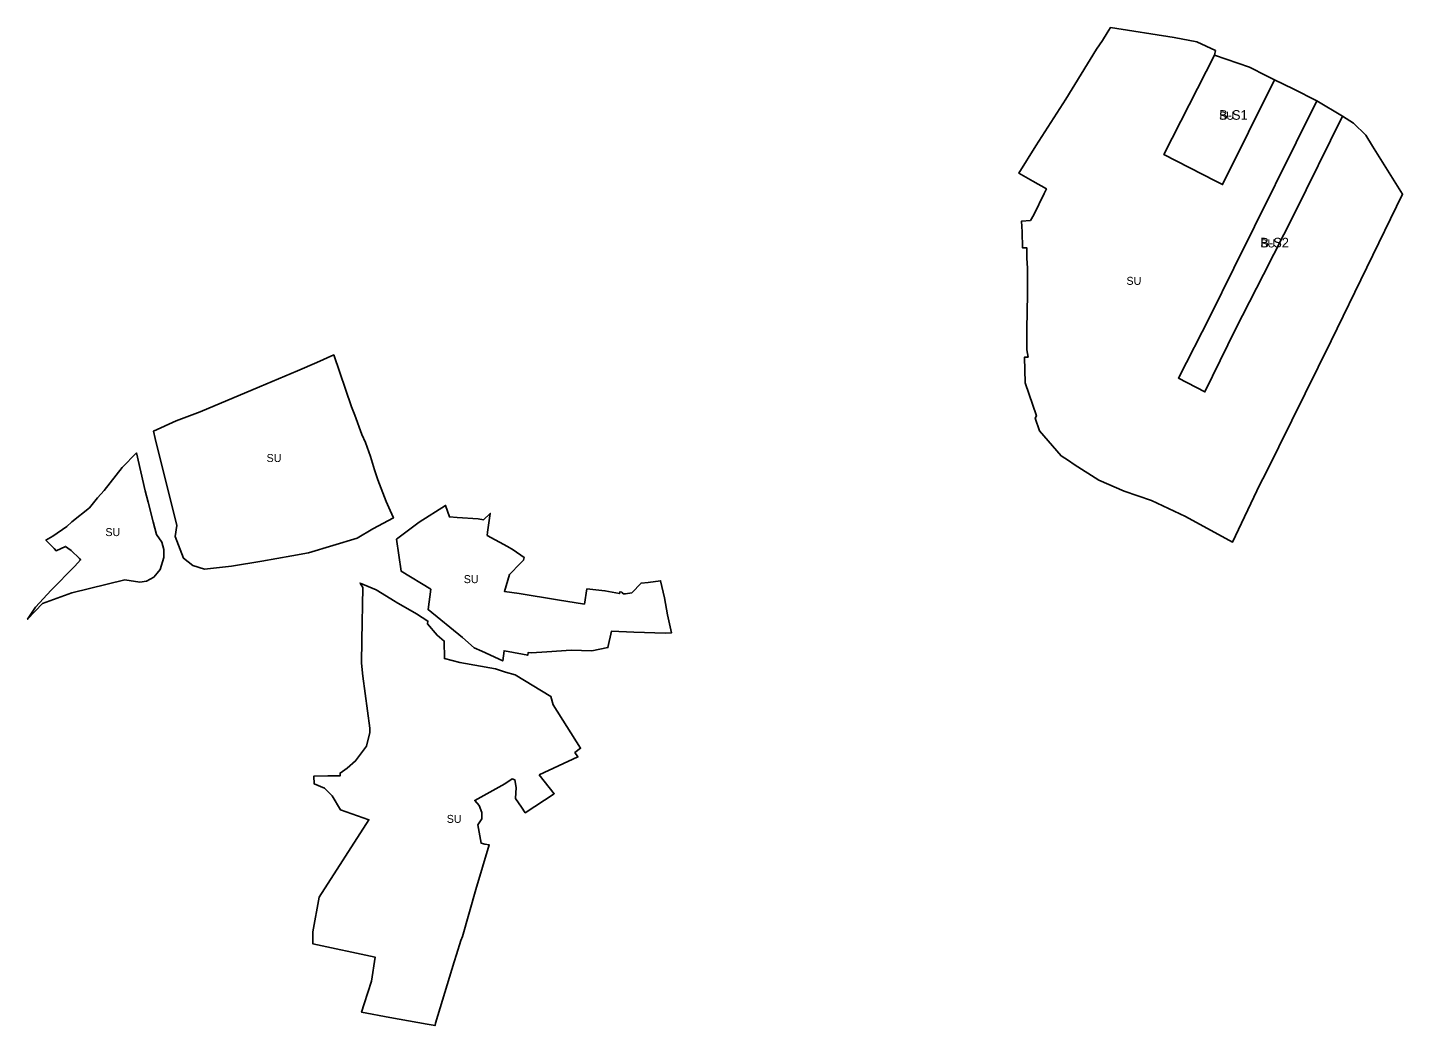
# Model space of a CAD drawing. Extents: x -532031 to -530019, y -1180236 to -1177276.
# Drawn here: x -531101 to -530242, y -1178607 to -1177983 of the extents above; entities that cross this region are included whole.
import ezdxf

# ---------------------------------------------------------------- set-up
doc = ezdxf.new("R2010")
doc.units = 0
for name, color, linetype in [('90480013', 7, 'Continuous'), ('90480023', 7, 'Continuous'), ('ID_navrh', 7, 'Continuous')]:
    doc.layers.add(name, color=color, linetype=linetype)

msp = doc.modelspace()

# ---------------------------------------------------------------- linework, layer by layer
at = {"layer": '90480013'}
for points in [[(-530359.2473, -1178079.28545), (-530354.5743, -1178081.67545), (-530322.1763, -1178016.13545), (-530310.4773, -1178021.80745), (-530295.6573, -1178029.24045), (-530347.5943, -1178133.89345), (-530362.2753, -1178163.84345), (-530382.1233, -1178202.62845), (-530365.5663, -1178211.24845), (-530346.3653, -1178172.03845), (-530328.9113, -1178137.78745), (-530309.7773, -1178100.23945), (-530279.6673, -1178038.82445), (-530272.6473, -1178043.32345), (-530265.0433, -1178050.75545), (-530260.7533, -1178057.60145), (-530242.0943, -1178087.56745), (-530286.6053, -1178179.34845), (-530327.4363, -1178262.14345), (-530331.3213, -1178269.18745), (-530348.3553, -1178305.24545), (-530377.6083, -1178289.27445), (-530398.9863, -1178279.22845), (-530415.9353, -1178273.23945), (-530431.9213, -1178266.47745), (-530447.2033, -1178256.72845), (-530450.7233, -1178254.20645), (-530455.4163, -1178251.34745), (-530468.9943, -1178235.54245), (-530471.6763, -1178227.80845), (-530470.8383, -1178226.29445), (-530477.8753, -1178205.60445), (-530478.2723, -1178189.46745), (-530476.0883, -1178189.46745), (-530476.9243, -1178184.96445), (-530476.7733, -1178171.79145), (-530476.5293, -1178150.45345), (-530476.3413, -1178134.01445), (-530476.7533, -1178127.57745), (-530476.9063, -1178121.16545), (-530479.5183, -1178121.22745), (-530479.7563, -1178111.25945), (-530480.2483, -1178104.64145), (-530474.6533, -1178104.17445), (-530472.5533, -1178100.49045), (-530465.9993, -1178087.34345), (-530464.6673, -1178084.36645), (-530473.1953, -1178079.44845), (-530481.9363, -1178074.52945), (-530471.2763, -1178057.42145), (-530452.4703, -1178028.18145), (-530433.2363, -1177996.96545), (-530429.6423, -1177991.66345), (-530426.6943, -1177986.79645), (-530424.5493, -1177983.47145), (-530384.7703, -1177989.73045), (-530370.5353, -1177992.46845), (-530359.0313, -1177997.94545), (-530359.6163, -1178000.68345), (-530391.1673, -1178062.95745)], [(-530973.8763, -1178320.29145), (-530990.7503, -1178322.07345), (-530998.0323, -1178319.75745), (-531003.8943, -1178315.30345), (-531009.0453, -1178301.76245), (-531007.9793, -1178294.81445), (-531021.4783, -1178240.47345), (-531022.7053, -1178235.84845), (-531008.4323, -1178229.27145), (-530993.3943, -1178223.78245), (-530956.3823, -1178208.15845), (-530932.6003, -1178198.07945), (-530920.5413, -1178192.87145), (-530909.9903, -1178188.16745), (-530898.8403, -1178220.60245), (-530896.8853, -1178225.83045), (-530892.3243, -1178237.81245), (-530890.1523, -1178242.82245), (-530887.1123, -1178251.75445), (-530884.5063, -1178260.03245), (-530882.4513, -1178266.30845), (-530877.2353, -1178279.79945), (-530874.7093, -1178285.46045), (-530872.6603, -1178290.05245), (-530885.4993, -1178296.92945), (-530895.3683, -1178302.65345), (-530925.7413, -1178311.91845), (-530936.1423, -1178313.72745), (-530955.0093, -1178317.00945)], [(-531017.3653, -1178305.16245), (-531016.2303, -1178309.71645), (-531016.2303, -1178314.72645), (-531018.5003, -1178322.24045), (-531020.4293, -1178324.63145), (-531022.3593, -1178327.02245), (-531026.8993, -1178329.52645), (-531031.2123, -1178330.20945), (-531040.5193, -1178328.84345), (-531073.6623, -1178336.81345), (-531092.0493, -1178343.64445), (-531101.3573, -1178353.43545), (-531096.2623, -1178345.92745), (-531086.5173, -1178335.30345), (-531071.8703, -1178320.14045), (-531068.1793, -1178316.33245), (-531068.9173, -1178315.48645), (-531074.0903, -1178310.50145), (-531076.1943, -1178309.03345), (-531077.5653, -1178307.86945), (-531083.4713, -1178310.61945), (-531084.7363, -1178309.13845), (-531087.1623, -1178306.70545), (-531089.8883, -1178303.97145), (-531085.4663, -1178301.51945), (-531076.8403, -1178295.37145), (-531073.6623, -1178292.41145), (-531062.7133, -1178283.82845), (-531057.6743, -1178277.56045), (-531053.4583, -1178272.96345), (-531042.1083, -1178258.48345), (-531033.2923, -1178249.40845), (-531027.7303, -1178273.15745), (-531026.0043, -1178280.13145), (-531022.8133, -1178292.41145), (-531020.7703, -1178300.38045)], [(-530819.7433, -1178290.70145), (-530816.3013, -1178291.26145), (-530812.1923, -1178287.22345), (-530813.9653, -1178298.97045), (-530814.1373, -1178301.03845), (-530801.3973, -1178308.03245), (-530797.8173, -1178309.99845), (-530791.0503, -1178314.80445), (-530791.4993, -1178316.55945), (-530793.1793, -1178318.44245), (-530800.2223, -1178325.50745), (-530803.3143, -1178336.01945), (-530794.0383, -1178337.39745), (-530770.1593, -1178341.36145), (-530753.3233, -1178343.94545), (-530751.7773, -1178334.46845), (-530740.5603, -1178335.55945), (-530731.3453, -1178337.35045), (-530731.0943, -1178336.21645), (-530729.9643, -1178336.46845), (-530729.0863, -1178337.47645), (-530727.5803, -1178337.47645), (-530723.6893, -1178336.84645), (-530717.8813, -1178330.82045), (-530713.4023, -1178330.41145), (-530705.7373, -1178329.31845), (-530703.2593, -1178340.00845), (-530701.4593, -1178350.73345), (-530698.9373, -1178361.95845), (-530702.6243, -1178362.20145), (-530722.4203, -1178361.45845), (-530736.4333, -1178360.93245), (-530738.6253, -1178371.09145), (-530748.6853, -1178373.06745), (-530761.5693, -1178372.72345), (-530776.8593, -1178373.75745), (-530786.3073, -1178374.44645), (-530788.4853, -1178374.22245), (-530788.7913, -1178375.95745), (-530800.9363, -1178373.62045), (-530803.5693, -1178373.11345), (-530804.3453, -1178379.44345), (-530817.4013, -1178373.41245), (-530822.2113, -1178371.34445), (-530829.5983, -1178364.79645), (-530851.0163, -1178347.33345), (-530849.3143, -1178334.70345), (-530867.8193, -1178323.40045), (-530870.7843, -1178303.41145), (-530856.6683, -1178292.82245), (-530840.1153, -1178282.22545), (-530837.7013, -1178289.48845), (-530832.8053, -1178289.75645)], [(-530781.5773, -1178450.76845), (-530772.1933, -1178462.48245), (-530790.2553, -1178474.42845), (-530792.7183, -1178470.82845), (-530796.4153, -1178465.42645), (-530795.9673, -1178458.50845), (-530796.8013, -1178453.90645), (-530798.4693, -1178453.27845), (-530803.0573, -1178456.20745), (-530821.8253, -1178466.66645), (-530819.1483, -1178469.81645), (-530817.4883, -1178474.25745), (-530817.4883, -1178478.14345), (-530819.9783, -1178482.02945), (-530817.7653, -1178493.40945), (-530815.5513, -1178493.96445), (-530812.7843, -1178494.51945), (-530821.1123, -1178522.41245), (-530829.6183, -1178551.77145), (-530830.6193, -1178554.28145), (-530833.2853, -1178563.02545), (-530834.6973, -1178567.65645), (-530846.3793, -1178605.97445), (-530846.6633, -1178607.38845), (-530851.6343, -1178606.49445), (-530874.8953, -1178602.30845), (-530892.5683, -1178599.12745), (-530890.9463, -1178593.78045), (-530886.3573, -1178579.75445), (-530884.1723, -1178564.63245), (-530923.0643, -1178556.30345), (-530923.0643, -1178548.85245), (-530919.1053, -1178527.18145), (-530888.0283, -1178478.74945), (-530905.7613, -1178472.62945), (-530910.8893, -1178463.79045), (-530915.7163, -1178459.01345), (-530922.2383, -1178456.29045), (-530922.3593, -1178451.41745), (-530913.7243, -1178451.20345), (-530905.9803, -1178451.40245), (-530905.9803, -1178449.61945), (-530901.6613, -1178446.56145), (-530896.3273, -1178441.97445), (-530889.4683, -1178432.80145), (-530887.3523, -1178424.19545), (-530887.3523, -1178421.56345), (-530891.6993, -1178389.06845), (-530892.6093, -1178380.96945), (-530892.5133, -1178366.47245), (-530891.8603, -1178333.58945), (-530893.4913, -1178330.80845), (-530883.3793, -1178335.06145), (-530871.6293, -1178342.35045), (-530870.9843, -1178342.75045), (-530858.2803, -1178350.00345), (-530851.0803, -1178354.58645), (-530851.3573, -1178356.25345), (-530845.4483, -1178363.37145), (-530840.8713, -1178367.09345), (-530840.8323, -1178378.02945), (-530831.2653, -1178380.45745), (-530808.9133, -1178384.42745), (-530802.6403, -1178386.55045), (-530796.5923, -1178388.22345), (-530774.2793, -1178401.61145), (-530772.8193, -1178406.84045), (-530755.7193, -1178434.03445), (-530759.2643, -1178436.75345), (-530757.3873, -1178439.47245)]]:
    msp.add_lwpolyline(points, close=True, dxfattribs=at)
at = {"layer": '90480023'}
for points in [[(-530327.0513, -1178013.78845), (-530322.1763, -1178016.13545), (-530354.5743, -1178081.67545), (-530359.2473, -1178079.28545), (-530391.1673, -1178062.95745), (-530359.6163, -1178000.68345), (-530337.7763, -1178008.31145)], [(-530347.5943, -1178133.89345), (-530295.6573, -1178029.24045), (-530279.6673, -1178038.82445), (-530309.7773, -1178100.23945), (-530328.9113, -1178137.78745), (-530346.3653, -1178172.03845), (-530365.5663, -1178211.24845), (-530382.1233, -1178202.62845), (-530362.2753, -1178163.84345)]]:
    msp.add_lwpolyline(points, close=True, dxfattribs=at)

# ---------------------------------------------------------------- texts
at = {"layer": '90480013'}
for rotation, p in [(0.00000001, (-530414.59183, -1178144.35845)), (0.00000002, (-530951.94622, -1178255.12045)), (0, (-531052.6791, -1178301.42195)), (359.99999998, (-530839.3918, -1178480.72493))]:
    msp.add_text('SU', height=5, rotation=rotation, dxfattribs=at).set_placement(p)
msp.add_text('SU', height=5, dxfattribs=at).set_placement((-530828.71886, -1178330.83445))
at = {"layer": '90480023'}
for rotation, p in [(0.00000005, (-530356.6718, -1178041.15728)), (359.99999994, (-530330.8953, -1178120.96288))]:
    msp.add_text('SU', height=5, rotation=rotation, dxfattribs=at).set_placement(p)
at = {"layer": 'ID_navrh'}
for s, rotation, p in [('B-S1', 359.99999996, (-530356.6718, -1178041.15728)), ('B-S2', 359.99999995, (-530330.8953, -1178120.96288))]:
    msp.add_text(s, height=6, rotation=rotation, dxfattribs=at).set_placement(p)

doc.saveas('drawing.dxf')
